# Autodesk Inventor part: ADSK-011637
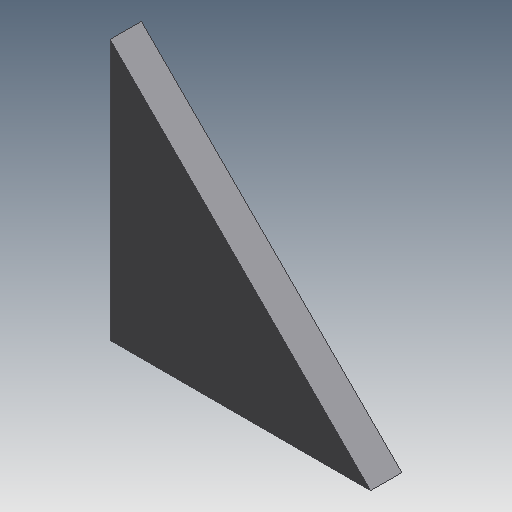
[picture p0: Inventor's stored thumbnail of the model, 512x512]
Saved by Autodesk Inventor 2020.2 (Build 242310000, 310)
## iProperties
Created: 2000-02
Part Number: ADSK-011637
Material: Pearson HRS
Document SubType Name: Modeling
Designer: sspink
Density: 7.83 g/cm^3
Appearance: Métal - Acier
Mass: 64.1554 g
Surface Area: 36.82 cm^2
Volume: 8.19353 cm^3
Control State: 0
Master: False
Checked Out: False
Shininess: 0.0
Length Units: 11269
Angle Units: 11279
Time Units: 11290
Mass Units: 11283
Length Display Precision: 3
Angle Display Precision: 2
Compacted: True
Cutlength: 2
Material Desc: FLAT,HRS,0.25 X 2.00
Material_Number: A084333
Dimensions: 50x6x50 mm
Mass: 0,059 kg
VLT_Material: Pearson HRS
Density: 0.0
Volumn: 0.0
Area: 0.0
PropertySet Name: Model Information
Author: sspink
Revision Number: -
Title: ADSK-011637
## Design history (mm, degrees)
node "Solide1"
  node "Extrusion1" dims "d2" = 6, "d3" = 0
sketch "Sketch1"
  geometry: L1 (0, 0)-(50, 0); L2 (0, 50)-(0, 0); L3 (0, 50)-(50, 0)
  constraints: 6 end point, 1 horizontal, 1 perpendicular
  dimensions: "d4" = 50 distance from line of L1.end L2 (= d6); "d6" = 50 distance of L2.start L1.start
node "Corps solides"
node "Corps surfaciques"
